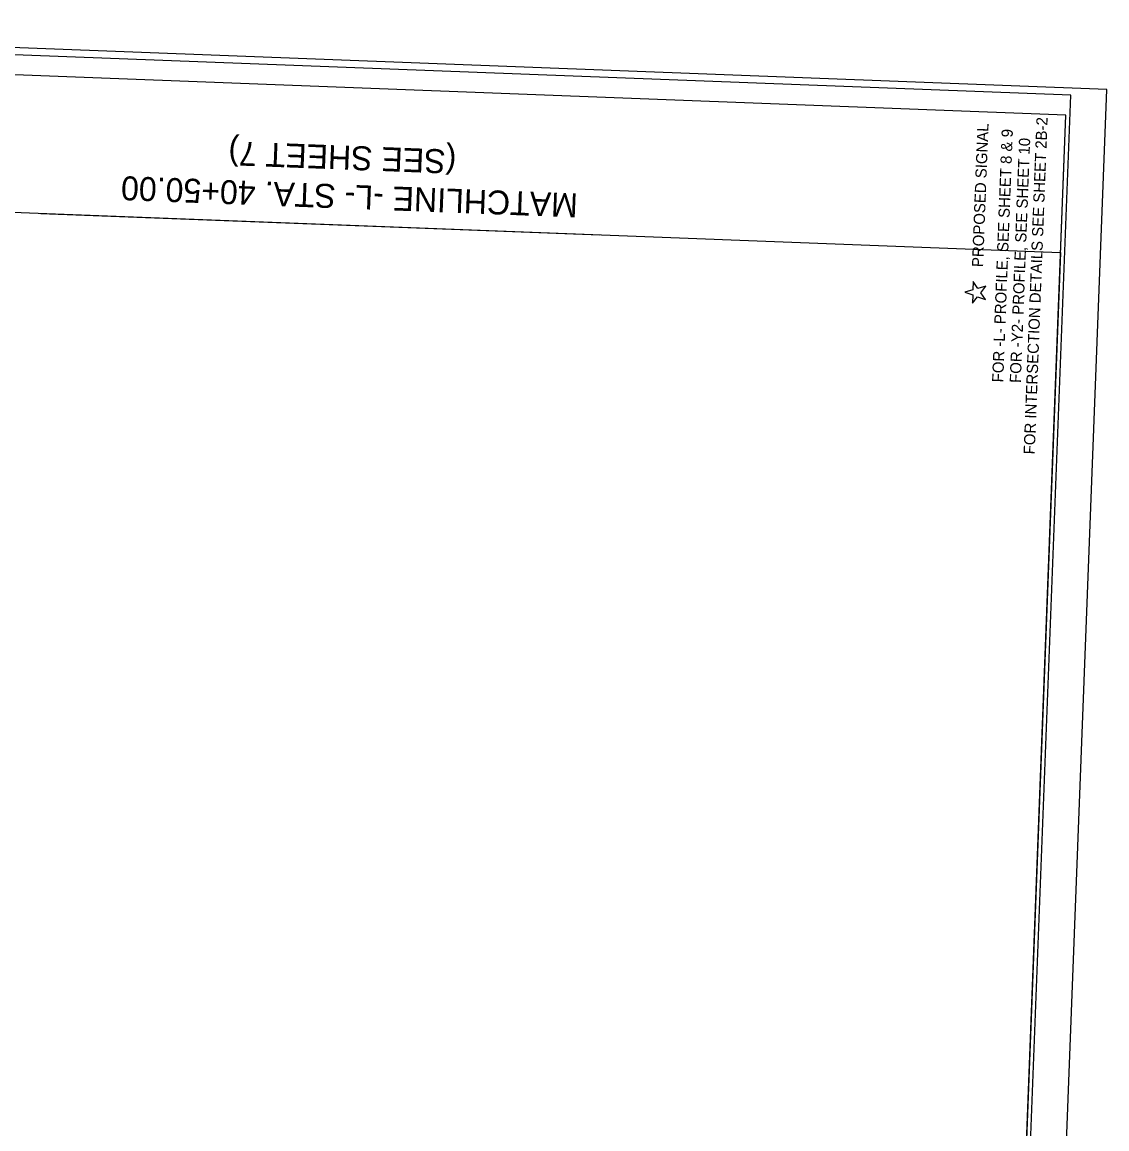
# Model space of a CAD drawing. Extents: x 2097096 to 2098260, y 686401 to 688363.
# Drawn here: x 2097581 to 2098260, y 687502 to 688194 of the extents above; entities that cross this region are included whole.
import ezdxf

# ---------------------------------------------------------------- set-up
doc = ezdxf.new("R2010")
doc.units = 0
for name, color, linetype in [('Default', 7, 'Continuous'), ('Matchline', 7, 'Continuous'), ('Matchline Text', 7, 'Continuous'), ('Prop Dimension Text', 7, 'Continuous'), ('Prop RDY Traffic Signal CELL', 7, 'Continuous'), ('Sheet Layout Plan Border', 7, 'Continuous'), ('Sheet Plot Border Inside CELL', 7, 'Continuous'), ('Sheet Plot Border Outside CELL', 7, 'Continuous'), ('Sheet Profile CELL', 7, 'Continuous')]:
    doc.layers.add(name, color=color, linetype=linetype)

msp = doc.modelspace()

# ---------------------------------------------------------------- linework, layer by layer
at = {"layer": 'Matchline'}
msp.add_line((2097592.68, 688074.63), (2097942.42, 688061.22), dxfattribs=at)
at = {"layer": 'Prop RDY Traffic Signal CELL'}
msp.add_lwpolyline([(2098175.79, 688023.56), (2098175.59, 688018.35), (2098178.82, 688022.45), (2098183.73, 688020.64), (2098180.82, 688024.99), (2098184.05, 688029.11), (2098179.02, 688027.68), (2098176.11, 688032.02), (2098175.91, 688026.8), (2098170.88, 688025.37), (2098175.79, 688023.56)], dxfattribs=at)
at = {"layer": 'Sheet Layout Plan Border'}
msp.add_lwpolyline([(2098179.19, 686705.44), (2097129.59, 686735.95), (2097177.17, 687976.48), (2097364.33, 687969.3), (2097368.7, 688083.22), (2098230.76, 688050.16)], close=True, dxfattribs=at)
at = {"layer": 'Sheet Plot Border Inside CELL'}
msp.add_lwpolyline([(2098173.22, 686483.26), (2098237.09, 688148.54), (2097182.76, 688188.97), (2097118.9, 686523.7)], close=True, dxfattribs=at)
at = {"layer": 'Sheet Plot Border Outside CELL'}
msp.add_lwpolyline([(2098195.16, 686469.41), (2098259.69, 688152.17), (2097160.5, 688194.33), (2097095.97, 686511.57)], close=True, dxfattribs=at)
at = {"layer": 'Sheet Profile CELL'}
msp.add_line((2098176.58, 686637.25), (2098234.06, 688136.14), dxfattribs=at)
msp.add_lwpolyline([(2097184.83, 688176.38), (2097127.35, 686677.48), (2098176.58, 686637.25), (2098234.06, 688136.14)], close=True, dxfattribs=at)

# ---------------------------------------------------------------- texts
at = {"layer": 'Default'}
msp.add_text('PROPOSED SIGNAL', height=7, rotation=87.8037, dxfattribs=at).set_placement((2098182.25, 688040.89))
at = {"layer": 'Matchline Text'}
for s, p in [('(SEE SHEET 7)', (2097852.91, 688114.35)), ('MATCHLINE -L- STA. 40+50.00', (2097928.97, 688087.04))]:
    msp.add_text(s, height=15, rotation=177.8037, dxfattribs=at).set_placement(p)
at = {"layer": 'Prop Dimension Text'}
for s, p in [('FOR INTERSECTION DETAILS SEE SHEET 2B-2', (2098214.57, 687923.7)), ('FOR -L- PROFILE, SEE SHEET 8 & 9', (2098194.85, 687968.77)), ('FOR -Y2- PROFILE, SEE SHEET 10', (2098205.88, 687968.4))]:
    msp.add_text(s, height=7, rotation=87.8037, dxfattribs=at).set_placement(p)

doc.saveas('drawing.dxf')
